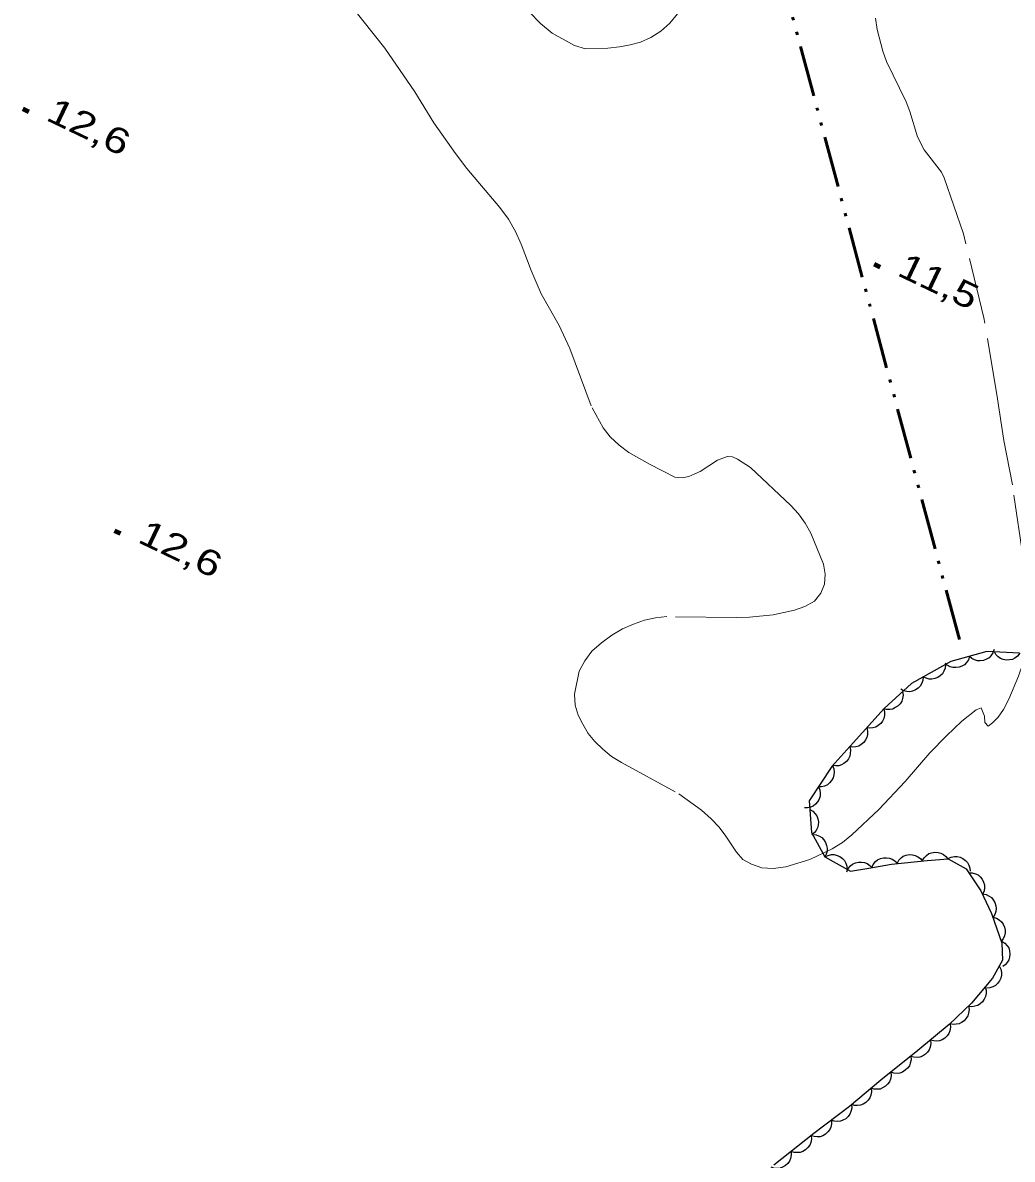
# Model space of a CAD drawing. Extents: x 355726 to 357533, y 5103782 to 5105258.
# Drawn here: x 356122.2 to 356180.4, y 5104866.1 to 5104933 of the extents above; entities that cross this region are included whole.
import ezdxf

# ---------------------------------------------------------------- set-up
doc = ezdxf.new("R2010")
doc.units = 0
doc.header["$LTSCALE"] = 0.6
for name, pattern in [('DASH_DOUBLE_DOT', [9.2, 5, -1.2, 0.3, -1.2, 0.3, -1.2]), ('DOT_DASHED', [7.7, 5, -1.2, 0.3, -1.2]), ('LONG_DASHED', [7.5, 6, -1.5])]:
    doc.linetypes.add(name, pattern=pattern)
for name, color, linetype, lineweight in [('2', 7, 'LONG_DASHED', 13), ('3', 7, 'Continuous', 140), ('4', 7, 'DASH_DOUBLE_DOT', 53), ('44', 7, 'Continuous', 25)]:
    doc.layers.add(name, color=color, linetype=linetype, lineweight=lineweight)

msp = doc.modelspace()

# ---------------------------------------------------------------- linework, layer by layer
at = {"layer": '2'}
for points in [[(356141.51, 5104933.98), (356143.49, 5104931.5), (356145.26, 5104928.92), (356146.38, 5104927.11), (356147.65, 5104925.3), (356148.32, 5104924.42), (356150.27, 5104922.12), (356150.77, 5104921.44), (356151.18, 5104920.71), (356151.52, 5104919.96), (356152.1, 5104918.42), (356152.7, 5104917.05), (356153.76, 5104915.18), (356154.38, 5104913.82), (356155.69, 5104910.33), (356156.34, 5104909.15), (356156.76, 5104908.62), (356157.28, 5104908.13), (356157.86, 5104907.7), (356159.08, 5104907.01), (356160.57, 5104906.26), (356161, 5104906.22), (356161.38, 5104906.3), (356161.74, 5104906.44), (356162.06, 5104906.59), (356163.07, 5104907.26), (356163.38, 5104907.38), (356163.67, 5104907.46), (356163.95, 5104907.45), (356164.26, 5104907.32), (356165.02, 5104906.82), (356167.39, 5104904.59), (356167.84, 5104904.09), (356168.23, 5104903.55), (356168.56, 5104902.96), (356169.31, 5104901.13), (356169.41, 5104900.54), (356169.37, 5104899.96), (356169.15, 5104899.43), (356168.78, 5104898.96), (356168.21, 5104898.65), (356167.6, 5104898.42), (356166.35, 5104898.15), (356164.96, 5104898.01), (356164.2, 5104897.99), (356160.1, 5104898.05), (356159.43, 5104897.98), (356158.77, 5104897.83), (356158.13, 5104897.61), (356157.49, 5104897.33), (356156.86, 5104896.96), (356156.24, 5104896.51), (356155.68, 5104896.01), (356155.27, 5104895.45), (356154.94, 5104894.84), (356154.65, 5104893.49), (356154.7, 5104892.84), (356154.88, 5104892.25), (356155.15, 5104891.71), (356155.47, 5104891.17), (356155.85, 5104890.69), (356156.32, 5104890.24), (356156.84, 5104889.82), (356157.43, 5104889.47), (356160.8, 5104887.61), (356162.13, 5104886.66), (356162.7, 5104886.15), (356163.17, 5104885.65), (356163.57, 5104885.13), (356164.19, 5104884.18), (356164.57, 5104883.76), (356165.08, 5104883.48), (356165.68, 5104883.26), (356166.35, 5104883.23), (356167.09, 5104883.32), (356168.5, 5104883.75), (356169.82, 5104884.38), (356170.44, 5104884.76), (356170.98, 5104885.2), (356172.58, 5104886.7), (356174.12, 5104888.34), (356175.58, 5104890.04), (356176.55, 5104891.03), (356177.46, 5104891.9), (356178.29, 5104892.57), (356178.6, 5104892.68), (356178.79, 5104892.19), (356178.81, 5104891.82), (356179, 5104891.61), (356179.27, 5104891.8), (356179.59, 5104892.13), (356179.91, 5104892.59)], [(356160.72, 5104933.51), (356160.26, 5104932.96), (356159.74, 5104932.5), (356159.16, 5104932.13), (356158.55, 5104931.86), (356157.93, 5104931.69), (356157.3, 5104931.58), (356156.62, 5104931.49), (356155.3, 5104931.46), (356154.66, 5104931.65), (356153.34, 5104932.38), (356152.66, 5104932.94), (356152, 5104933.62)], [(356179.91, 5104892.59), (356180.23, 5104893.19), (356180.8, 5104894.55), (356181.05, 5104895.28), (356181.3, 5104896.69), (356181.35, 5104898.01), (356181.28, 5104899.4), (356181.04, 5104901.63), (356180.43, 5104905.8), (356179.92, 5104908.42), (356179.56, 5104910.87), (356178.76, 5104915.62), (356177.55, 5104920.58), (356176.42, 5104923.86), (356176.25, 5104924.2), (356175.24, 5104925.51), (356174.84, 5104926.28), (356174.4, 5104927.78), (356174.18, 5104928.34), (356173.03, 5104930.71), (356172.8, 5104931.32), (356172.48, 5104932.59), (356172.38, 5104933.26)]]:
    msp.add_lwpolyline(points, dxfattribs=at)
at = {"layer": '3'}
for p, q in [((356122.18, 5104927.92), (356122.54, 5104927.75)), ((356172.29, 5104918.79), (356172.65, 5104918.62)), ((356127.58, 5104903.1), (356127.94, 5104902.93))]:
    msp.add_line(p, q, dxfattribs=at)
at = {"layer": '4'}
msp.add_lwpolyline([(356177.31, 5104896.7), (356162.28, 5104952.8), (356155.35, 5104996.88), (356148.26, 5105046.53), (356143.19, 5105083.66), (356158.61, 5105101.48), (356161.38, 5105105.71)], dxfattribs=at)
at = {"layer": '44', "linetype": 'DOT_DASHED'}
msp.add_lwpolyline([(356180.86, 5104895.9), (356178.93, 5104895.99), (356176.81, 5104895.4), (356174.5, 5104894.12), (356172.88, 5104892.65), (356170.87, 5104890.41), (356169.8, 5104889.23), (356168.47, 5104887.21), (356168.61, 5104885.34), (356169.39, 5104883.91), (356170.9, 5104883.07), (356171.99, 5104883.25), (356173.32, 5104883.49), (356175.42, 5104883.7), (356176.66, 5104883.79), (356177.71, 5104883.2), (356178.58, 5104881.92), (356179.21, 5104880.57), (356179.82, 5104878.84), (356179.85, 5104877.84), (356179.26, 5104876.78), (356178.02, 5104875.3), (356176.72, 5104874.05), (356174.87, 5104872.51), (356172.69, 5104870.77), (356170.84, 5104869.23), (356168.75, 5104867.63), (356165.82, 5104865.33)], dxfattribs=at)
at = {"layer": '44'}
for points in [[(356177.91, 5104895.71), (356177.84, 5104895.51), (356177.73, 5104895.34), (356177.61, 5104895.22), (356177.46, 5104895.13), (356177.29, 5104895.07), (356177.1, 5104895.05), (356176.93, 5104895.05), (356176.77, 5104895.1), (356176.6, 5104895.19), (356176.47, 5104895.3)], [(356179.36, 5104896.11), (356179.29, 5104895.91), (356179.17, 5104895.74), (356179.06, 5104895.62), (356178.91, 5104895.54), (356178.73, 5104895.47), (356178.54, 5104895.45), (356178.38, 5104895.45), (356178.21, 5104895.5), (356178.05, 5104895.59), (356177.91, 5104895.71)], [(356180.87, 5104895.9), (356180.74, 5104895.73), (356180.58, 5104895.61), (356180.44, 5104895.53), (356180.26, 5104895.5), (356180.08, 5104895.49), (356179.89, 5104895.53), (356179.74, 5104895.58), (356179.59, 5104895.68), (356179.46, 5104895.82), (356179.37, 5104895.97)], [(356176.5, 5104895.23), (356176.48, 5104895.02), (356176.4, 5104894.83), (356176.32, 5104894.69), (356176.19, 5104894.56), (356176.04, 5104894.46), (356175.86, 5104894.4), (356175.7, 5104894.36), (356175.53, 5104894.37), (356175.35, 5104894.42), (356175.18, 5104894.5)], [(356175.18, 5104894.5), (356175.17, 5104894.29), (356175.09, 5104894.1), (356175.01, 5104893.96), (356174.88, 5104893.84), (356174.73, 5104893.73), (356174.55, 5104893.67), (356174.39, 5104893.63), (356174.21, 5104893.65), (356174.03, 5104893.69), (356173.87, 5104893.77)], [(356173.97, 5104893.64), (356174, 5104893.43), (356173.97, 5104893.23), (356173.92, 5104893.07), (356173.83, 5104892.92), (356173.7, 5104892.79), (356173.54, 5104892.69), (356173.39, 5104892.61), (356173.22, 5104892.59), (356173.03, 5104892.59), (356172.86, 5104892.63)], [(356172.86, 5104892.63), (356172.91, 5104892.43), (356172.9, 5104892.22), (356172.87, 5104892.06), (356172.79, 5104891.9), (356172.68, 5104891.76), (356172.53, 5104891.64), (356172.39, 5104891.55), (356172.22, 5104891.5), (356172.04, 5104891.49), (356171.86, 5104891.51)], [(356171.86, 5104891.51), (356171.91, 5104891.31), (356171.9, 5104891.11), (356171.87, 5104890.94), (356171.79, 5104890.79), (356171.68, 5104890.64), (356171.53, 5104890.52), (356171.39, 5104890.43), (356171.22, 5104890.39), (356171.03, 5104890.37), (356170.86, 5104890.4)], [(356170.86, 5104890.4), (356170.91, 5104890.19), (356170.89, 5104889.99), (356170.86, 5104889.83), (356170.78, 5104889.67), (356170.67, 5104889.52), (356170.52, 5104889.41), (356170.38, 5104889.32), (356170.21, 5104889.27), (356170.03, 5104889.26), (356169.85, 5104889.28)], [(356169.84, 5104889.29), (356169.92, 5104889.1), (356169.94, 5104888.9), (356169.93, 5104888.73), (356169.88, 5104888.56), (356169.79, 5104888.4), (356169.66, 5104888.26), (356169.54, 5104888.15), (356169.38, 5104888.08), (356169.2, 5104888.04), (356169.02, 5104888.04)], [(356169.02, 5104888.04), (356169.1, 5104887.85), (356169.12, 5104887.64), (356169.11, 5104887.48), (356169.05, 5104887.31), (356168.97, 5104887.15), (356168.84, 5104887.01), (356168.71, 5104886.9), (356168.55, 5104886.83), (356168.37, 5104886.79), (356168.19, 5104886.79)], [(356168.51, 5104886.7), (356168.69, 5104886.6), (356168.83, 5104886.45), (356168.92, 5104886.32), (356168.98, 5104886.15), (356169.01, 5104885.97), (356168.99, 5104885.78), (356168.96, 5104885.62), (356168.88, 5104885.46), (356168.76, 5104885.32), (356168.62, 5104885.21)], [(356168.67, 5104885.22), (356168.88, 5104885.2), (356169.07, 5104885.13), (356169.21, 5104885.04), (356169.33, 5104884.92), (356169.44, 5104884.76), (356169.5, 5104884.58), (356169.53, 5104884.42), (356169.52, 5104884.25), (356169.47, 5104884.07), (356169.39, 5104883.91)], [(356169.39, 5104883.91), (356169.58, 5104884), (356169.78, 5104884.04), (356169.95, 5104884.04), (356170.12, 5104884), (356170.28, 5104883.93), (356170.43, 5104883.81), (356170.55, 5104883.69), (356170.63, 5104883.53), (356170.69, 5104883.36), (356170.7, 5104883.18)], [(356170.68, 5104883.03), (356170.77, 5104883.22), (356170.9, 5104883.38), (356171.03, 5104883.48), (356171.19, 5104883.56), (356171.37, 5104883.6), (356171.56, 5104883.6), (356171.72, 5104883.58), (356171.88, 5104883.51), (356172.04, 5104883.41), (356172.16, 5104883.28)], [(356172.16, 5104883.28), (356172.24, 5104883.47), (356172.38, 5104883.63), (356172.5, 5104883.74), (356172.66, 5104883.81), (356172.84, 5104883.86), (356173.03, 5104883.86), (356173.19, 5104883.84), (356173.35, 5104883.78), (356173.51, 5104883.68), (356173.64, 5104883.55)], [(356173.64, 5104883.52), (356173.74, 5104883.71), (356173.88, 5104883.85), (356174.01, 5104883.95), (356174.18, 5104884.01), (356174.36, 5104884.04), (356174.55, 5104884.03), (356174.71, 5104884), (356174.87, 5104883.92), (356175.02, 5104883.81), (356175.13, 5104883.67)], [(356175.13, 5104883.68), (356175.23, 5104883.86), (356175.38, 5104884), (356175.52, 5104884.1), (356175.68, 5104884.15), (356175.87, 5104884.18), (356176.06, 5104884.16), (356176.22, 5104884.13), (356176.37, 5104884.04), (356176.52, 5104883.93), (356176.63, 5104883.79)], [(356176.63, 5104883.81), (356176.82, 5104883.9), (356177.02, 5104883.93), (356177.18, 5104883.94), (356177.35, 5104883.9), (356177.52, 5104883.82), (356177.67, 5104883.7), (356177.79, 5104883.58), (356177.87, 5104883.43), (356177.92, 5104883.25), (356177.94, 5104883.07)], [(356177.86, 5104882.98), (356178.07, 5104882.98), (356178.26, 5104882.92), (356178.41, 5104882.86), (356178.54, 5104882.74), (356178.66, 5104882.6), (356178.74, 5104882.42), (356178.79, 5104882.27), (356178.79, 5104882.09), (356178.77, 5104881.91), (356178.7, 5104881.74)], [(356178.67, 5104881.73), (356178.88, 5104881.69), (356179.06, 5104881.6), (356179.2, 5104881.51), (356179.31, 5104881.38), (356179.4, 5104881.22), (356179.45, 5104881.03), (356179.48, 5104880.87), (356179.45, 5104880.7), (356179.4, 5104880.52), (356179.31, 5104880.37)], [(356179.28, 5104880.36), (356179.49, 5104880.31), (356179.66, 5104880.2), (356179.79, 5104880.09), (356179.89, 5104879.95), (356179.96, 5104879.78), (356180, 5104879.59), (356180.01, 5104879.43), (356179.96, 5104879.26), (356179.89, 5104879.09), (356179.78, 5104878.94)], [(356179.82, 5104878.95), (356179.99, 5104878.84), (356180.13, 5104878.68), (356180.22, 5104878.55), (356180.27, 5104878.38), (356180.29, 5104878.19), (356180.26, 5104878), (356180.22, 5104877.85), (356180.13, 5104877.7), (356180.01, 5104877.56), (356179.86, 5104877.45)], [(356179.66, 5104877.5), (356179.75, 5104877.31), (356179.79, 5104877.11), (356179.8, 5104876.95), (356179.75, 5104876.78), (356179.68, 5104876.61), (356179.56, 5104876.46), (356179.44, 5104876.34), (356179.29, 5104876.26), (356179.11, 5104876.2), (356178.93, 5104876.19)], [(356178.83, 5104876.26), (356178.88, 5104876.06), (356178.88, 5104875.86), (356178.85, 5104875.69), (356178.78, 5104875.53), (356178.67, 5104875.38), (356178.53, 5104875.26), (356178.39, 5104875.17), (356178.23, 5104875.12), (356178.04, 5104875.09), (356177.86, 5104875.11)], [(356177.84, 5104875.13), (356177.88, 5104874.92), (356177.85, 5104874.72), (356177.81, 5104874.56), (356177.72, 5104874.41), (356177.6, 5104874.27), (356177.44, 5104874.16), (356177.3, 5104874.09), (356177.12, 5104874.06), (356176.94, 5104874.05), (356176.76, 5104874.09)], [(356176.76, 5104874.09), (356176.78, 5104873.88), (356176.75, 5104873.68), (356176.69, 5104873.52), (356176.59, 5104873.38), (356176.46, 5104873.25), (356176.29, 5104873.15), (356176.14, 5104873.09), (356175.97, 5104873.07), (356175.78, 5104873.08), (356175.61, 5104873.13)], [(356175.61, 5104873.13), (356175.63, 5104872.92), (356175.59, 5104872.72), (356175.54, 5104872.56), (356175.44, 5104872.42), (356175.31, 5104872.29), (356175.14, 5104872.19), (356174.99, 5104872.13), (356174.82, 5104872.11), (356174.63, 5104872.12), (356174.46, 5104872.17)], [(356174.45, 5104872.18), (356174.47, 5104871.97), (356174.42, 5104871.77), (356174.37, 5104871.61), (356174.26, 5104871.47), (356174.13, 5104871.35), (356173.96, 5104871.25), (356173.81, 5104871.19), (356173.64, 5104871.17), (356173.45, 5104871.19), (356173.28, 5104871.24)], [(356173.28, 5104871.24), (356173.3, 5104871.03), (356173.25, 5104870.83), (356173.2, 5104870.68), (356173.09, 5104870.54), (356172.96, 5104870.41), (356172.79, 5104870.32), (356172.64, 5104870.25), (356172.46, 5104870.24), (356172.28, 5104870.25), (356172.11, 5104870.3)], [(356172.12, 5104870.29), (356172.14, 5104870.08), (356172.1, 5104869.89), (356172.04, 5104869.73), (356171.94, 5104869.59), (356171.81, 5104869.46), (356171.65, 5104869.36), (356171.5, 5104869.29), (356171.32, 5104869.27), (356171.14, 5104869.28), (356170.96, 5104869.33)], [(356170.97, 5104869.33), (356170.98, 5104869.12), (356170.93, 5104868.92), (356170.87, 5104868.77), (356170.77, 5104868.63), (356170.63, 5104868.5), (356170.46, 5104868.41), (356170.31, 5104868.35), (356170.13, 5104868.34), (356169.95, 5104868.36), (356169.78, 5104868.42)], [(356169.78, 5104868.42), (356169.79, 5104868.21), (356169.74, 5104868.01), (356169.68, 5104867.86), (356169.57, 5104867.72), (356169.44, 5104867.59), (356169.27, 5104867.5), (356169.12, 5104867.44), (356168.94, 5104867.43), (356168.76, 5104867.45), (356168.59, 5104867.5)], [(356168.59, 5104867.5), (356168.6, 5104867.29), (356168.56, 5104867.1), (356168.5, 5104866.94), (356168.39, 5104866.8), (356168.26, 5104866.67), (356168.09, 5104866.58), (356167.94, 5104866.52), (356167.76, 5104866.51), (356167.58, 5104866.52), (356167.41, 5104866.58)], [(356167.41, 5104866.58), (356167.42, 5104866.37), (356167.38, 5104866.17), (356167.32, 5104866.01), (356167.21, 5104865.87), (356167.08, 5104865.75), (356166.91, 5104865.66), (356166.76, 5104865.59), (356166.58, 5104865.58), (356166.4, 5104865.6), (356166.23, 5104865.65)]]:
    msp.add_lwpolyline(points, dxfattribs=at)

# ---------------------------------------------------------------- texts
at = {"layer": '3'}
for s, width, p in [('12,6   ', 1.3, (356123.47, 5104927.3)), ('11,5   ', 1.25, (356173.58, 5104918.16)), ('12,6   ', 1.3, (356128.87, 5104902.46))]:
    msp.add_text(s, height=1.5, rotation=334.423, dxfattribs=dict(at, width=width)).set_placement(p)

doc.saveas('drawing.dxf')
